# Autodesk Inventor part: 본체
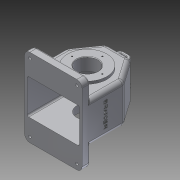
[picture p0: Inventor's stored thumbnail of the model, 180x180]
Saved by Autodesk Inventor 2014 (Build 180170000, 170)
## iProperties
Created: 2016-12
Part Number: 본체
Material: 알루미늄 6061
Document SubType Name: Modeling
Designer: 702
Density: 2.71 g/cm^3
Appearance: 알루미늄 - 평지
Mass: 1064.64 g
Surface Area: 1144.04 cm^2
Volume: 392.855 cm^3
Author: 702
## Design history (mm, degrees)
sketch "스케치1"
  geometry: L1 (-55, 15)-(-55, -65); L2 (-55, -65)-(55, -65); L3 (55, -65)-(55, 15); L4 (55, 15)-(23.491, 60); L5 (23.491, 60)-(-23.491, 60); L6 (-23.491, 60)-(-55, 15); 1 further point
  constraints: 12 end point, 2 parallel, 1 perpendicular, 1 vertical
  dimensions: "d0" = 35 deg angle of L1 L6; "d1" = 35 deg angle of L4 L3; "d4" = 80 distance from line of L1.start L2; "d5" = 80 distance of L3.end L2.end; "d6" = 65 distance from line of L2 point (0, 0); "d10" = 125 distance between parallel lines of L5 L2; "d11" = 110 distance of L1.end L2.end; "d12" = 55 distance from line of L1 point (0, 0)
extrude "돌출1" new body sketch "스케치1" stored distance "d8" = 77; taper "d9" = 0 deg
sketch "스케치2"
  geometry: C1 r 37.5 at (0, 0); 1 further point
  constraints: 1 centre point, 1 coincident
  dimensions: "d13" = 75 diameter of C1
extrude "돌출2" join sketch "스케치2" distance "d14" = 5; taper "d15" = 0 deg
sketch "스케치3"
  geometry: C1 r 31 at (0, 0); 1 further point
  constraints: 1 centre point, 1 coincident
  dimensions: "d16" = 62 diameter of C1
extrude "돌출3" join sketch "스케치3" distance "d17" = 10; taper "d18" = 0 deg
sketch "스케치4"
  geometry: L1 (110, -77)-(110, 0) reference; L2 (0, 0)-(110, 0) reference; L3 (0, -77)-(0, 0) reference; L4 (110, -77)-(0, -77) reference; L5 (0, -113.5)-(110, -113.5); L6 (110, -113.5)-(110, 36.5); L7 (110, 36.5)-(0, 36.5); L8 (0, 36.5)-(0, -113.5); L9 (0, -113.5)-(110, 36.5); L10 (110, -113.5)-(0, 36.5); 1 further point
  constraints: 12 end point, 2 midpoint, 2 parallel, 1 horizontal, 1 perpendicular
  dimensions: "d19" = 150 distance of L5.end L6.end; "d20" = 110 distance of L5.start L5.end
extrude "돌출4" join sketch "스케치4" distance "d21" = 15; taper "d22" = 0 deg
sketch "스케치5"
  geometry: L1 (-23.491, 60)-(23.491, 60) reference; L2 (-55, 15)-(-23.491, 60) reference; L3 (-55, -50)-(-55, 15) reference; L4 (23.491, 60)-(55, 15) reference; L5 (55, 15)-(55, -50) reference; L6 (55, -65)-(55, -50) reference; L7 (-55, -65)-(-55, -50) reference; L8 (-55, -65)-(55, -65) reference; L9 (50, 13.424)-(20.888, 55); L10 (20.888, 55)-(-20.888, 55); L11 (-20.888, 55)-(-50, 13.424); L12 (-50, 13.424)-(-50, -50); L13 (-50, -50)-(-50, -65); L14 (50, -65)-(50, -46.738); L15 (50, -46.738)-(50, 13.424); L16 (-50, -65)-(50, -65); 1 further point
  constraints: 16 end point, 2 point on line, 1 perpendicular, 5 other
  dimensions: "d23" = 5 distance between parallel lines of L10 L1; "d24" = 5 distance between parallel lines of L15 L5
extrude "돌출5" cut sketch "스케치5" stored distance "d25" = 67; taper "d26" = 0 deg
node "작업 평면1"
sketch "스케치6"
  geometry: C1 r 27 at (0, 0); 1 further point
  constraints: 1 centre point, 1 coincident
  dimensions: "d28" = 54 diameter of C1
extrude "돌출7" join sketch "스케치6" stored distance "d31" = 24; taper "d32" = 45 deg
sketch "스케치7"
  geometry: C1 r 37.5 at (0, 0) reference; C2 r 20 at (0, 0)
  constraints: 1 centre point, 1 coincident
  dimensions: "d33" = 40 diameter of C2
extrude "돌출8" cut sketch "스케치7" distance "d34" = 24; taper "d35" = 0 deg
sketch "스케치8"
  geometry: C1 r 20 at (0, 0) reference; 1 further point
  dimensions: "d36" = 29 distance of point (0, 29) C1.centre
hole "구멍1" sketch "스케치8" at (0, 29) diameter "d37" = 2.459; stored, may be unused: countersink angle "d41" = 90 deg, drill point angle "d43" = 118 deg; dims "d38" = 6, "d39" = 4, "d40" = 2, "d42" = 8
sketch "스케치9"
  geometry: C1 r 31 at (0, 0) reference; C2 r 20 at (0, 0)
  constraints: 1 centre point, 1 coincident
  dimensions: "d47" = 40 diameter of C2
extrude "돌출9" cut sketch "스케치9" distance "d48" = 15; taper "d49" = 0 deg
sketch "스케치10"
  geometry: C1 r 20 at (0, 0) reference; 1 further point
  constraints: 1 vertical alignment
  dimensions: "d50" = 26 distance of point (0, 26) C1.centre
hole "구멍2" sketch "스케치10" at (0, 26) diameter "d51" = 2.459; stored, may be unused: countersink angle "d55" = 90 deg, drill point angle "d57" = 118 deg; dims "d52" = 6, "d53" = 4, "d54" = 2, "d56" = 8
sketch "스케치11"
  geometry: L1 (46.981, 0)-(0, 0) reference; L2 (10.991, 20.5)-(35.991, 20.5); L3 (35.991, 20.5)-(35.991, 12.5); L4 (35.991, 12.5)-(10.991, 12.5); L5 (10.991, 12.5)-(10.991, 20.5); 1 further point
  constraints: 8 end point, 2 parallel, 1 horizontal, 1 perpendicular
  dimensions: "d61" = 25 distance of L3.end L4.end; "d62" = 12.5 distance from line of L5 point (23.491, 38.5); "d63" = 8 distance of L2.end L3.end; "d64" = 12.5 distance between parallel lines of L1 L4
extrude "돌출10" join sketch "스케치11" distance "d65" = 15; taper "d66" = 0 deg
fillet "모깎기1" dims "d72" = 8
sketch "스케치13"
  geometry: L1 (0, 0)-(0, 7) reference; L2 (25, 0)-(0, 0) reference; L3 (25, 0)-(25, 7) reference; L4 (8, 15)-(17, 15) reference; L5 (20, 7)-(20, 0); L6 (5, 0)-(5, 7); L7 (8, 10)-(17, 10); A1 r 8 centre (8, 7) between (8, 15) and (0, 7) reference; A2 r 8 centre (17, 7) between (25, 7) and (17, 15) reference; A3 r 3 centre (17, 7) between (20, 7) and (17, 10); A4 r 3 centre (8, 7) between (8, 10) and (5, 7); 1 further point
  constraints: 6 end point, 4 point on circle, 2 centre point, 2 point on line, 1 other
  dimensions: "d73" = 5 radial gap between concentric circles of A2 A3; "d74" = 10 distance between parallel lines of L2 L7; "d75" = 5 distance between parallel lines of L3 L5; "d76" = 5 distance between parallel lines of L1 L6
extrude "돌출12" cut sketch "스케치13" distance "d77" = 15; taper "d78" = 0 deg
fillet "모깎기2" dims "d79" = 1
fillet "모깎기3" dims "d80" = 10
sketch "스케치15"
  geometry: A1 r 10 centre (10, -26.5) between (0, -26.5) and (10, -36.5) reference; 2 further points
  constraints: 1 coincident
hole "구멍3" sketch "스케치15" at (10, -26.5) diameter "d81" = 5; stored, may be unused: countersink angle "d85" = 90 deg, drill point angle "d87" = 0 deg; dims "d82" = 6, "d83" = 12, "d84" = 5, "d86" = 18
fillet "모깎기4" dims "d88" = 10
chamfer "모따기1" distance "d91" = 1; stored, may be unused: second distance "d92" = 2, angle "d93" = 45 deg
sketch "스케치16"
  geometry: L1 (130, 0)-(0, 0) reference; L2 (26.5, 76.847)-(26.5, 18) reference; 2 further points
  constraints: 1 other
  dimensions: "d94" = 45 distance from line of L1 point (65, 45); "d95" = 38.5 distance from line of L2 point (65, 45)
feature "엠보싱1" sketch "스케치16" dims "d96" = 0.5, "d97" = 0
fillet "모깎기7" dims "d98" = 1
fillet "모깎기8" dims "d99" = 1
fillet "모깎기9" dims "d100" = 3
fillet "모깎기10" dims "d101" = 3
fillet "모깎기12" dims "d103" = 8
fillet "모깎기13" dims "d104" = 3
node "솔리드1"
pattern_circular "원형 패턴1" dims angle "d45" = 360 deg
pattern_circular "원형 패턴2" dims angle "d59" = 360 deg
mirror "대칭1"
mirror "대칭2"
mirror "대칭3"
other parameters: "d27" = -24
